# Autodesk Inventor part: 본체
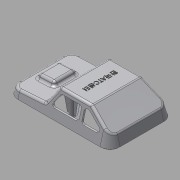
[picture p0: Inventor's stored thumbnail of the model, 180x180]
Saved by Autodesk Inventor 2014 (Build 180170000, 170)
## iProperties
Created: 2015-05
Part Number: 본체
Material: ABS 플라스틱
Document SubType Name: Modeling
Designer: Administrator
Density: 1.06 g/cm^3
Appearance: 매끄러움 - 흰색
Mass: 32.6559 g
Surface Area: 311.511 cm^2
Volume: 30.8074 cm^3
Author: Administrator
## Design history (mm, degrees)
sketch "스케치2"
  geometry: L1 (-49, 38)-(49, 38); L2 (61, 26)-(61, -26); L3 (49, -38)-(-49, -38); L4 (-61, -26)-(-61, 26); L5 (-61, 38)-(61, -38); L6 (61, 38)-(-61, -38); A1 r 12 centre (-49, 26) between (-49, 38) and (-61, 26); A2 r 12 centre (-49, -26) between (-61, -26) and (-49, -38); A3 r 12 centre (49, -26) between (49, -38) and (61, -26); A4 r 12 centre (49, 26) between (61, 26) and (49, 38); 1 further point
  constraints: 12 end point, 8 point on circle, 8 point on line, 8 tangent, 4 centre point, 3 equal radius, 2 midpoint, 2 parallel, 1 horizontal, 1 perpendicular
  dimensions: "d0" = 122 distance of L5.end L6.end; "d1" = 76 distance of L6.start L5.end; "d2" = 12 radius of A1
extrude "돌출1" new body sketch "스케치2" distance "d3" = 30; taper "d4" = -15 deg
sketch "스케치3"
  geometry: L1 (-31, 30)-(-61, 30); L2 (-61, 30)-(-61, 10); L3 (-61, 10)-(-31, 30); L4 (49, 30)-(-49, 30) reference; 2 further points
  constraints: 6 end point, 1 collinear, 1 horizontal, 1 perpendicular, 1 vertical alignment
  dimensions: "d5" = 20 distance of L1.end L2.end; "d6" = 30 distance of L1.start L1.end
extrude "돌출2" cut sketch "스케치3" stored distance "d7" = 30; taper "d8" = 0 deg
sketch "스케치4"
  geometry: L1 (61, 8)-(19, 10.201); L2 (19, 10.201)-(6.628, 30); L3 (6.628, 30)-(61, 30); L4 (61, 30)-(61, 8); L5 (-49, 0)-(49, 0) reference; L6 (49, 30)-(-31, 30) reference; 3 further points
  constraints: 8 end point, 1 collinear, 1 horizontal, 1 midpoint, 1 perpendicular, 1 vertical alignment
  dimensions: "d10" = 8 distance from line of L5 L1.start; "d12" = 125 deg angle of L1 L2; "d13" = 3 deg angle of L5 L1; "d16" = 42 horizontal distance of L1.end L1.start
extrude "돌출3" cut sketch "스케치4" stored distance "d14" = 30; taper "d15" = 0 deg
sketch "스케치5"
  geometry: L1 (-39.881, 9.267)-(-39.881, 61.267) reference; L2 (-31.476, 48.267)-(-11.476, 48.267); L3 (-11.476, 48.267)-(-11.476, 22.267); L4 (-11.476, 22.267)-(-31.476, 22.267); L5 (-31.476, 22.267)-(-31.476, 48.267); L6 (-42.476, 61.267)-(-42.476, 9.267) reference; 3 further points
  constraints: 8 end point, 2 midpoint, 2 parallel, 1 horizontal, 1 horizontal alignment, 1 perpendicular
  dimensions: "d18" = 26 distance of L4.end L2.start; "d19" = 20 distance of L2.start L2.end; "d119" = 11 distance from line of L6 point (-31.476, 35.267)
extrude "돌출4" join sketch "스케치5" distance "d20" = 5; taper "d21" = 0 deg
fillet "모깎기1" dims "d22" = 3
fillet "모깎기2" dims "d23" = 3
fillet "모깎기3" dims "d24" = 3
fillet "모깎기4" dims "d25" = 3
sketch "스케치6"
  geometry: L1 (4.965, 30)-(-30.092, 30) reference; L2 (18.172, 11.526)-(7.51, 28.59) reference; L3 (-31.756, 29.496)-(-50.664, 16.891) reference; L4 (2.194, 25)-(-17.77, 25); L5 (10.362, 14.59)-(4.738, 23.59); L6 (7.818, 10)-(-17.77, 10); L7 (-20.77, 13)-(-20.77, 22); L8 (-30.242, 24.496)-(-43.742, 15.496); L9 (-28.578, 25)-(-26.986, 25); L10 (-23.986, 22)-(-23.986, 13); L11 (-26.986, 10)-(-42.078, 10); A1 r 3 centre (7.818, 13) between (7.818, 10) and (10.362, 14.59); A2 r 3 centre (2.194, 22) between (4.738, 23.59) and (2.194, 25); A3 r 3 centre (-17.77, 22) between (-17.77, 25) and (-20.77, 22); A4 r 3 centre (-17.77, 13) between (-20.77, 13) and (-17.77, 10); A5 r 3 centre (-26.986, 13) between (-26.986, 10) and (-23.986, 13); A6 r 3 centre (-26.986, 22) between (-23.986, 22) and (-26.986, 25); A7 r 3 centre (-28.578, 22) between (-28.578, 25) and (-30.242, 24.496); A8 r 3 centre (-42.078, 13) between (-43.742, 15.496) and (-42.078, 10); 7 further points
  constraints: 16 end point, 16 point on circle, 16 tangent, 12 point on line, 8 centre point, 7 equal radius, 5 parallel, 3 perpendicular
  dimensions: "d26" = 5 distance between parallel lines of L4 L1; "d27" = 5 distance between parallel lines of L5 L2; "d28" = 34 distance of point (13.23, 10) point (-20.77, 10); "d29" = 15 distance of point (-20.77, 25) point (-20.77, 10); "d30" = 5 distance between parallel lines of L8 L3; "d31" = 5 distance between parallel lines of L9 L1; "d32" = 15 distance of point (-23.986, 25) point (-23.986, 10); "d33" = 28 distance of point (-51.986, 10) point (-23.986, 10); "d35" = 3 radius of A1
sketch "스케치7"
  geometry: L1 (61, 26)-(61, -26) reference; L2 (-49, 38)-(49, 38) reference; L3 (-61, -26)-(-61, 26) reference; L4 (49, -38)-(-49, -38) reference; A1 r 12 centre (49, 26) between (61, 26) and (49, 38) reference; A2 r 12 centre (-49, 26) between (-49, 38) and (-61, 26) reference; A3 r 12 centre (-49, -26) between (-61, -26) and (-49, -38) reference; A4 r 12 centre (49, -26) between (49, -38) and (61, -26) reference; 1 further point
feature "쉘1" dims "d34" = 2
extrude "돌출5" cut sketch "스케치6" stored distance "d36" = 5; taper "d37" = 0 deg
node "작업 평면1"
sketch "스케치8"
  geometry: A1 r 4 centre (21, 0) between (25, 0) and (17, 0); A2 r 4 centre (10, 0) between (14, 0) and (6, 0); 3 further points
  constraints: 4 point on circle, 2 centre point, 7 other
  dimensions: "d39" = 4 radius of A1; "d40" = 4 radius of A2; "d41" = 10 distance of A2.centre point (0, 0); "d42" = 11 distance of A2.centre A1.centre
extrude "돌출6" join sketch "스케치8" stored distance "d43" = 5; taper "d44" = 0 deg
chamfer "모따기1" distance "d45" = 1; stored, may be unused: second distance "d46" = 2, angle "d47" = 45 deg
sketch "스케치9"
  geometry: L1 (-4.965, -27.66)-(-4.965, 27.66) reference; L2 (61, -26)-(61, 26) reference; 3 further points
  constraints: 1 horizontal alignment, 1 midpoint, 1 other
  dimensions: "d48" = 50 distance from line of L2 point (11, 0)
feature "엠보싱1" sketch "스케치9" dims "d0" = 122, "d1" = 76, "d2" = 12, "d49" = 0.5, "d50" = 0
sketch "스케치10"
  geometry: L1 (58.929, 26)-(58.929, -26) reference; L2 (49, -35.929)-(-49, -35.929) reference; L3 (-58.929, -26)-(-58.929, 26) reference; L4 (-49, 35.929)-(49, 35.929) reference; L5 (49, 36.929)-(-49, 36.929); L6 (-59.929, 26)-(-59.929, -26); L7 (-49, -36.929)-(49, -36.929); L8 (59.929, -26)-(59.929, 26); A1 r 9.929 centre (49, -26) between (49, -35.929) and (58.929, -26) reference; A2 r 9.929 centre (-49, -26) between (-58.929, -26) and (-49, -35.929) reference; A3 r 9.929 centre (-49, 26) between (-49, 35.929) and (-58.929, 26) reference; A4 r 9.929 centre (49, 26) between (58.929, 26) and (49, 35.929) reference; A5 r 10.929 centre (-49, 26) between (-49, 36.929) and (-59.929, 26); A6 r 10.929 centre (-49, -26) between (-59.929, -26) and (-49, -36.929); A7 r 10.929 centre (49, -26) between (49, -36.929) and (59.929, -26); A8 r 10.929 centre (49, 26) between (59.929, 26) and (49, 36.929); 1 further point
  constraints: 8 end point, 8 point on circle, 4 centre point, 7 other
  dimensions: "d51" = 1 distance between parallel lines of L4 L5
extrude "돌출7" join sketch "스케치10" distance "d52" = 1; taper "d53" = 0 deg
sketch "스케치11"
  geometry: C1 r 3 at (0, 22); C2 r 3 at (-40, 0); C3 r 3 at (0, -22); C4 r 3 at (40, 0); 1 further point
  constraints: 4 centre point, 2 horizontal alignment, 2 vertical alignment
  dimensions: "d54" = 6 diameter of C3; "d55" = 6 diameter of C1; "d56" = 6 diameter of C2; "d57" = 6 diameter of C4; "d58" = 22 distance of C1.centre point (0, 0); "d59" = 44 distance of C1.centre C3.centre; "d60" = 40 distance of point (0, 0) C4.centre; "d61" = 40 distance of point (0, 0) C2.centre
extrude "돌출8" join sketch "스케치11" stored distance "d62" = 1; taper "d63" = 2 deg
node "작업 평면2"
sketch "스케치12"
  geometry: L1 (-44.994, -1)-(-34.994, -1); L2 (-34.994, -1)-(-34.994, 1); L3 (-34.994, 1)-(-44.994, 1); L4 (-44.994, 1)-(-44.994, -1); L5 (-44.994, -1)-(-34.994, 1); L6 (-34.994, -1)-(-44.994, 1); L7 (-5, 21)-(5, 21); L8 (5, 21)-(5, 23); L9 (5, 23)-(-5, 23); L10 (-5, 23)-(-5, 21); L11 (-5, 21)-(5, 23); L12 (5, 21)-(-5, 23); L13 (34.913, -1)-(44.913, -1); L14 (44.913, -1)-(44.913, 1); L15 (44.913, 1)-(34.913, 1); L16 (34.913, 1)-(34.913, -1); L17 (34.913, -1)-(44.913, 1); L18 (44.913, -1)-(34.913, 1); L19 (-5, -23)-(5, -23); L20 (5, -23)-(5, -21); L21 (5, -21)-(-5, -21); L22 (-5, -21)-(-5, -23); L23 (-5, -23)-(5, -21); L24 (5, -23)-(-5, -21); C1 r 3.978 at (0, -22) reference; C2 r 3.978 at (0, 22) reference; 3 further points; 2 other entities
  constraints: 48 end point, 8 midpoint, 8 parallel, 4 horizontal, 4 perpendicular, 2 other
  dimensions: "d65" = 2 distance of L1.end L2.end; "d66" = 10 distance of L2.end L3.end; "d67" = 10 distance of L7.start L7.end; "d68" = 2 distance of L7.end L8.end; "d69" = 10 distance of L14.end L15.end; "d70" = 2 distance of L13.end L14.end; "d71" = 10 distance of L20.end L21.end; "d72" = 2 distance of L19.end L20.end
extrude "돌출9" join sketch "스케치12" stored distance "d73" = 2; taper "d74" = 2.5 deg
sketch "스케치18"
  geometry: C1 r 3 at (0, 0) reference; C2 r 3 at (-40, 22) reference; C3 r 3 at (0, 44) reference; C4 r 3 at (40, 22) reference; 5 further points
  constraints: 4 coincident
hole "구멍1" sketch "스케치18" at (-40, 22), (0, 0), (40, 22), (0, 44) diameter "d94" = 3.242; stored, may be unused: countersink angle "d98" = 90 deg, drill point angle "d100" = 118 deg; dims "d95" = 9, "d96" = 4, "d97" = 2, "d99" = 11
sketch "스케치20"
  geometry: L1 (-44.913, 2)-(-45.605, 17.86) reference; L2 (-34.913, 2)-(-33.879, 25.677) reference; L3 (-30.092, 30)-(4.965, 30) reference; L4 (-34.913, 2)-(-30.333, 27.97); L5 (-44.913, 2)-(-47.488, 16.604); L6 (-49.555, 15.226)-(-30.646, 27.832) reference; A1 r 1 centre (-30.092, 27) between (-30.092, 28) and (-30.646, 27.832) reference; 1 further point
  constraints: 4 end point, 1 point on circle, 1 point on line
  dimensions: "d105" = 80 deg angle of L4 L3; "d106" = 100 deg angle of L5 L3
extrude "돌출16" join sketch "스케치20" stored distance "d107" = 2; taper "d108" = 0 deg
node "작업 평면3"
sketch "스케치21"
  geometry: L1 (-5, 2)-(-6.135, 28) reference; L2 (5, 2)-(6.095, 27.079) reference; L3 (-30.092, 30)-(4.965, 30) reference; L4 (-5, 2)-(-9.585, 28); L5 (5, 2)-(8.69, 22.927); L6 (5.813, 27.53)-(16.476, 10.466) reference; L7 (-30.092, 28)-(4.965, 28) reference; 1 further point
  constraints: 4 end point, 2 point on line
  dimensions: "d110" = 100 deg angle of L5 L3; "d111" = 100 deg angle of L3 L4
extrude "돌출17" join sketch "스케치21" stored distance "d112" = 2; taper "d113" = 0 deg
node "작업 평면4"
sketch "스케치22"
  geometry: L1 (-5, 2)-(-6.135, 28) reference; L2 (5, 2)-(6.095, 27.079) reference; L3 (-30.092, 30)-(4.965, 30) reference; L4 (-5, 2)-(-9.585, 28); L5 (5, 2)-(8.69, 22.927); L6 (5.813, 27.53)-(16.476, 10.466) reference; L7 (-30.092, 28)-(4.965, 28) reference; 1 further point
  constraints: 4 end point, 2 point on line
  dimensions: "d115" = 100 deg angle of L5 L3; "d116" = 100 deg angle of L3 L4
extrude "돌출18" join sketch "스케치22" stored distance "d117" = 0; taper "d118" = 0 deg
sketch "스케치23"
  geometry: L1 (34.994, 2)-(34.54, 12.391) reference; L2 (44.994, 2)-(45.423, 11.82) reference; L3 (-30.092, 30)-(4.965, 30) reference; L4 (34.994, 2)-(33.149, 12.464); L5 (44.994, 2)-(46.713, 11.753); L6 (33.613, 12.439)-(47.594, 11.707) reference; L7 (34.994, 2)-(34.994, 12.367); L8 (34.994, 12.367)-(33.149, 12.464); A1 r 1 centre (33.477, 11.445) between (33.53, 12.444) and (32.501, 11.663) reference; A2 r 3 centre (33.477, 11.445) between (33.634, 14.441) and (30.55, 12.099) reference; 2 further points
  constraints: 8 end point, 2 point on line, 1 collinear, 1 perpendicular, 1 point on circle
  dimensions: "d120" = 100 deg angle of L4 L3; "d121" = 100 deg angle of L3 L5
extrude "돌출19" join sketch "스케치23" stored distance "d122" = 2; taper "d123" = 0 deg
node "솔리드1"
mirror "대칭1"
node "투영된 루프2"
node "투영된 루프3"
node "투영된 루프4"
other parameters: "d38" = -63, "d64" = 2, "d109" = 22, "d114" = -22
